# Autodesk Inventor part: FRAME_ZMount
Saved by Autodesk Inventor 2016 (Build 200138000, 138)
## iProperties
Created: 2016-03
Part Number: FRAME_ZMount
Material: Generic
Document SubType Name: Modeling
Designer: bongo_000
Density: 1 g/cm^3
Appearance: Default
Author: bongo_000
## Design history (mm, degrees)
feature "SOLID1"
body "Solid1"
